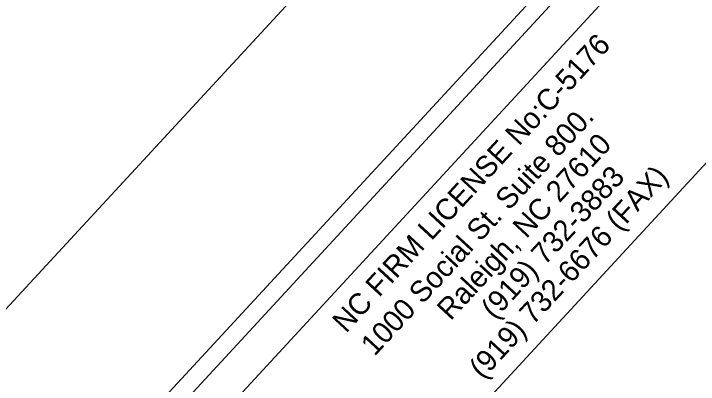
# Model space of a CAD drawing. Extents: x 1767460 to 1770129, y 996106 to 1001438.
# Drawn here: x 1768921.4 to 1769038.8, y 1001174.1 to 1001237.5 of the extents above; entities that cross this region are included whole.
import ezdxf

# ---------------------------------------------------------------- set-up
doc = ezdxf.new("R2010")
doc.units = 0
for name, color, linetype in [('E_NCDOT_Terrain_Model_Contour_Minor', 7, 'Continuous'), ('E_NCDOT_Terrain_Model_Points_Low', 7, 'Continuous'), ('E_NCDOT_Terrain_Model_Triangle_Vertices', 7, 'Continuous'), ('P_NCDOT_Terrain_Points_High', 7, 'Continuous'), ('P_RDY_Edge_of_Travel', 7, 'Continuous'), ('P_RDY_TL_Edge_of_Travel_Sub', 7, 'Continuous')]:
    doc.layers.add(name, color=color, linetype=linetype)

msp = doc.modelspace()

# ---------------------------------------------------------------- linework, layer by layer
at = {"layer": 'E_NCDOT_Terrain_Model_Contour_Minor'}
msp.add_lwpolyline([(1768744.05, 999038.07), (1770128.77, 1000536.12), (1769152.55, 1001438.49), (1767767.83, 999940.44)], close=True, dxfattribs=at)
at = {"layer": 'E_NCDOT_Terrain_Model_Points_Low'}
msp.add_lwpolyline([(1767804.38, 999935.46), (1769171.05, 1001413.98), (1770107.33, 1000548.53), (1768740.66, 999070.01)], close=True, dxfattribs=at)
at = {"layer": 'E_NCDOT_Terrain_Model_Triangle_Vertices'}
msp.add_lwpolyline([(1769163.02, 1001400.87), (1767932.52, 1000069.67), (1768864.37, 999208.32), (1770094.87, 1000539.52)], close=True, dxfattribs=at)
at = {"layer": 'P_NCDOT_Terrain_Points_High'}
msp.add_lwpolyline([(1769163.02, 1001400.87), (1767932.52, 1000069.67), (1768864.37, 999208.32), (1769639.43, 1000046.81), (1769513.61, 1000163.11), (1769964.83, 1000651.25), (1769968.19, 1000656.62)], close=True, dxfattribs=at)
at = {"layer": 'P_RDY_Edge_of_Travel'}
msp.add_lwpolyline([(1768868.65, 1001073.25), (1769032.76, 1001250.8), (1769056.07, 1001229.26), (1768891.95, 1001051.71)], close=True, dxfattribs=at)

# ---------------------------------------------------------------- texts
at = {"layer": 'P_RDY_TL_Edge_of_Travel_Sub'}
for s, p in [('NC FIRM LICENSE No:C-5176', (1768978.38, 1001182.71)), ('1000 Social St. Suite 800.', (1768983.25, 1001178.75)), ('Raleigh, NC 27610', (1768996.3, 1001184.85)), ('(919) 732-6676 (FAX)', (1769001.83, 1001174.8)), ('(919) 732-3883', (1769003.86, 1001185.02))]:
    msp.add_text(s, height=3.6266, rotation=47.2512, dxfattribs=at).set_placement(p)

doc.saveas('drawing.dxf')
